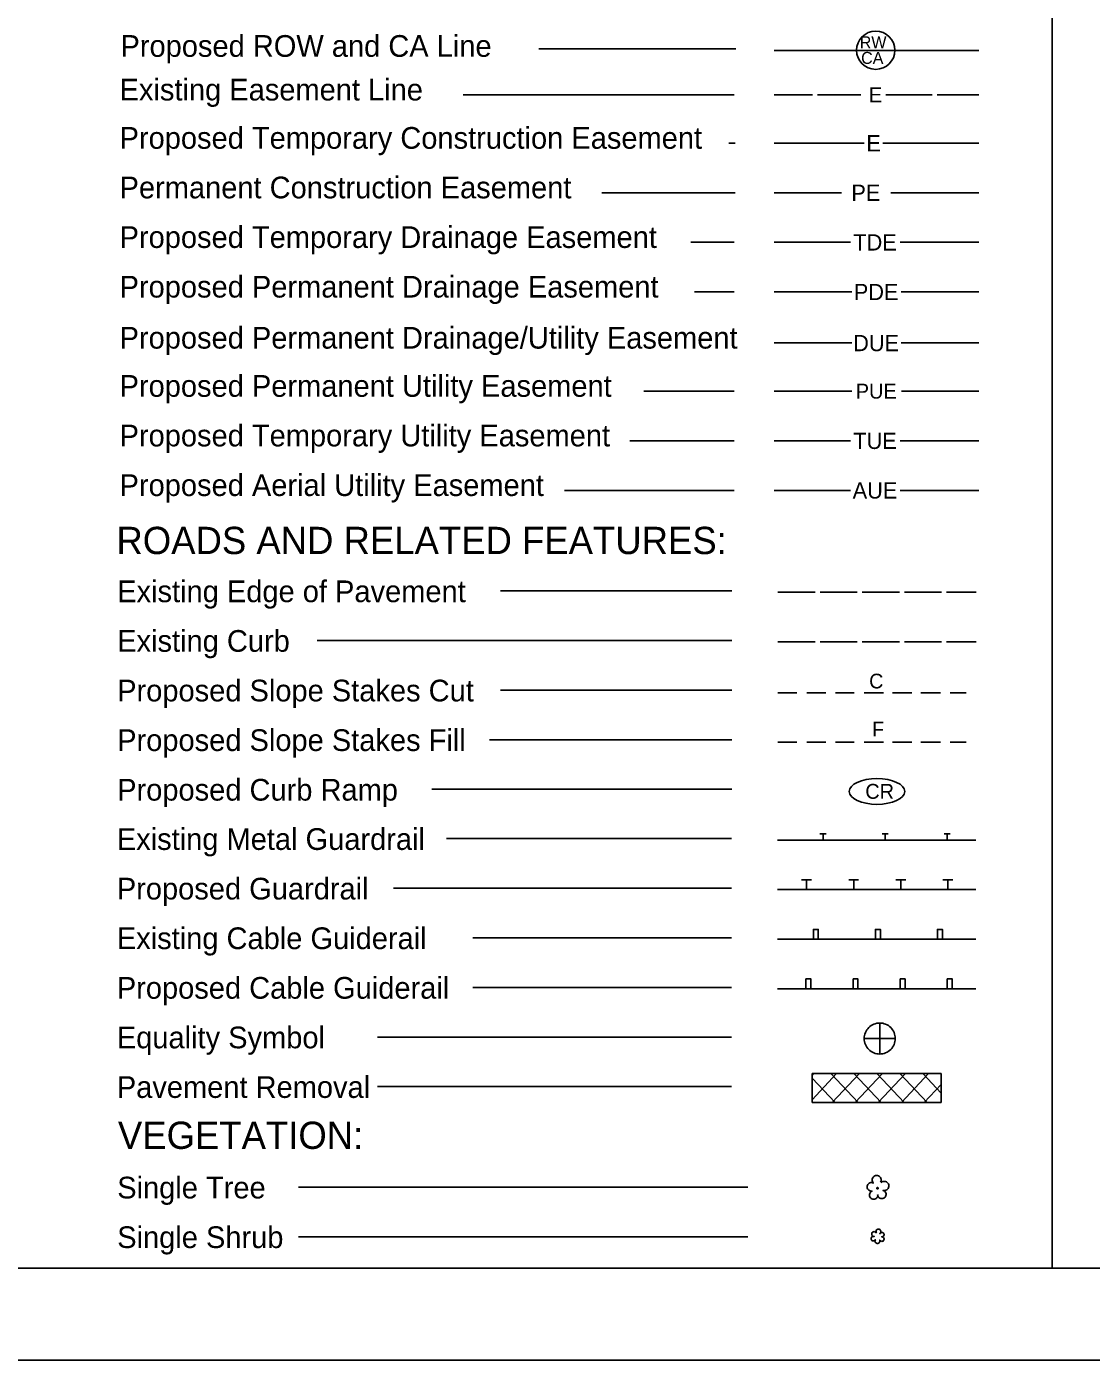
# Model space of a CAD drawing. Extents: x 0 to 3, y 0 to 1.83.
# Drawn here: x 0.722 to 1.443, y 0 to 0.904 of the extents above; entities that cross this region are included whole.
import ezdxf

# ---------------------------------------------------------------- set-up
doc = ezdxf.new("R2010")
doc.units = 0
for name, color, linetype in [('P_RDY_Easement_Permanent', 7, 'Continuous'), ('P_RDY_Easement_Permanent_Drainage_Utility', 7, 'Continuous'), ('Sheet PE Seal Cell', 7, 'Continuous'), ('Sheet_Plan', 7, 'Continuous'), ('Sheet_Symbology', 7, 'Continuous'), ('z - Construction', 7, 'Continuous')]:
    doc.layers.add(name, color=color, linetype=linetype)

msp = doc.modelspace()

# ---------------------------------------------------------------- linework, layer by layer
at = {"layer": 'P_RDY_Easement_Permanent'}
for p, q in [((1.22812, 0.7916), (1.27392, 0.7916)), ((1.30722, 0.7916), (1.35302, 0.7916)), ((1.35302, 0.7916), (1.36684, 0.7916))]:
    msp.add_line(p, q, dxfattribs=at)
at = {"layer": 'P_RDY_Easement_Permanent_Drainage_Utility'}
for p, q in [((1.22812, 0.68973), (1.28075, 0.68973)), ((1.31438, 0.68973), (1.36684, 0.68973))]:
    msp.add_line(p, q, dxfattribs=at)
at = {"layer": 'Sheet PE Seal Cell'}
msp.add_ellipse((1.2979, 0.38567), major_axis=(0.01886, 0), ratio=0.462467, dxfattribs=at)
at = {"layer": 'Sheet_Plan'}
msp.add_line((0.0625, 0.0625), (2.77079, 0.0625), dxfattribs=at)
at = {"layer": 'Sheet_Symbology'}
for p, q in [((1.20222, 0.88925), (1.06878, 0.88925)), ((1.22813, 0.88795), (1.36686, 0.88795)), ((1.20116, 0.85794), (1.01745, 0.85794)), ((1.22812, 0.85794), (1.2542, 0.85794)), ((1.25756, 0.85794), (1.28699, 0.85794)), ((1.30381, 0.85794), (1.33534, 0.85794)), ((1.3387, 0.85794), (1.36684, 0.85794)), ((1.20181, 0.82523), (1.19757, 0.82523)), ((1.22812, 0.82523), (1.23251, 0.82523)), ((1.23251, 0.82523), (1.28926, 0.82523)), ((1.30187, 0.82523), (1.35863, 0.82523)), ((1.35863, 0.82523), (1.36684, 0.82523)), ((1.20181, 0.7916), (1.11133, 0.7916)), ((1.20116, 0.75797), (1.17174, 0.75797)), ((1.22812, 0.75797), (1.23375, 0.75797)), ((1.23375, 0.75797), (1.27999, 0.75797)), ((1.31362, 0.75797), (1.35987, 0.75797)), ((1.35987, 0.75797), (1.36684, 0.75797)), ((1.20116, 0.72434), (1.17424, 0.72434)), ((1.22812, 0.72434), (1.2345, 0.72434)), ((1.2345, 0.72434), (1.28075, 0.72434)), ((1.31438, 0.72434), (1.36062, 0.72434)), ((1.36062, 0.72434), (1.36684, 0.72434)), ((1.20116, 0.65706), (1.13993, 0.65706)), ((1.22812, 0.65706), (1.23457, 0.65706)), ((1.23457, 0.65706), (1.28081, 0.65706)), ((1.31444, 0.65706), (1.36069, 0.65706)), ((1.36069, 0.65706), (1.36684, 0.65706)), ((1.20116, 0.62343), (1.1303, 0.62343)), ((1.22812, 0.62343), (1.23375, 0.62343)), ((1.23375, 0.62343), (1.27999, 0.62343)), ((1.31362, 0.62343), (1.35987, 0.62343)), ((1.35987, 0.62343), (1.36684, 0.62343)), ((1.20116, 0.5898), (1.08605, 0.5898)), ((1.22812, 0.5898), (1.23375, 0.5898)), ((1.23375, 0.5898), (1.27999, 0.5898)), ((1.31362, 0.5898), (1.35987, 0.5898)), ((1.35987, 0.5898), (1.36684, 0.5898)), ((1.19954, 0.52165), (1.04275, 0.52165)), ((1.2307, 0.52068), (1.25592, 0.52068)), ((1.25929, 0.52068), (1.28451, 0.52068)), ((1.28787, 0.52068), (1.3131, 0.52068)), ((1.31646, 0.52068), (1.34168, 0.52068)), ((1.34505, 0.52068), (1.36523, 0.52068)), ((1.19954, 0.48802), (0.91847, 0.48802)), ((1.2307, 0.48705), (1.25592, 0.48705)), ((1.25929, 0.48705), (1.28451, 0.48705)), ((1.28787, 0.48705), (1.3131, 0.48705)), ((1.31646, 0.48705), (1.34168, 0.48705)), ((1.34505, 0.48705), (1.36523, 0.48705)), ((1.19954, 0.45439), (1.04284, 0.45439)), ((1.2307, 0.45262), (1.24348, 0.45262)), ((1.26316, 0.45262), (1.25046, 0.45262)), ((1.28249, 0.45262), (1.26971, 0.45262)), ((1.30225, 0.45262), (1.28914, 0.45262)), ((1.32151, 0.45262), (1.30847, 0.45262)), ((1.34093, 0.45262), (1.32773, 0.45262)), ((1.35825, 0.45262), (1.34749, 0.45262)), ((1.19954, 0.42075), (1.03519, 0.42075)), ((1.2307, 0.41899), (1.24348, 0.41899)), ((1.26316, 0.41899), (1.25046, 0.41899)), ((1.28249, 0.41899), (1.26971, 0.41899)), ((1.30225, 0.41899), (1.28914, 0.41899)), ((1.32151, 0.41899), (1.30847, 0.41899)), ((1.34093, 0.41899), (1.32773, 0.41899)), ((1.35825, 0.41899), (1.34749, 0.41899)), ((1.19954, 0.38712), (0.9962, 0.38712)), ((1.19928, 0.35369), (1.00617, 0.35369)), ((1.23044, 0.35273), (1.36496, 0.35273)), ((1.25926, 0.35693), (1.26346, 0.35693)), ((1.26136, 0.35273), (1.26136, 0.35693)), ((1.3013, 0.35693), (1.3055, 0.35693)), ((1.3034, 0.35273), (1.3034, 0.35693)), ((1.34333, 0.35693), (1.34754, 0.35693)), ((1.34544, 0.35273), (1.34544, 0.35693)), ((1.24679, 0.32574), (1.25352, 0.32574)), ((1.25015, 0.3191), (1.25015, 0.32574)), ((1.27874, 0.32574), (1.28547, 0.32574)), ((1.2821, 0.3191), (1.2821, 0.32574)), ((1.31069, 0.32574), (1.31742, 0.32574)), ((1.31405, 0.3191), (1.31405, 0.32574)), ((1.34264, 0.32574), (1.34937, 0.32574)), ((1.346, 0.3191), (1.346, 0.32574)), ((1.19928, 0.32006), (0.97019, 0.32006)), ((1.36496, 0.3191), (1.23044, 0.3191)), ((1.19928, 0.28643), (1.02389, 0.28643)), ((1.23044, 0.28546), (1.36496, 0.28546)), ((1.19928, 0.2528), (1.02389, 0.2528)), ((1.23044, 0.25183), (1.36496, 0.25183)), ((1.29976, 0.22869), (1.29976, 0.21818)), ((1.19928, 0.21917), (0.95945, 0.21917)), ((1.28925, 0.21818), (1.29976, 0.21818)), ((1.29976, 0.21818), (1.29976, 0.20767)), ((1.29976, 0.21818), (1.31027, 0.21818)), ((1.2539, 0.19443), (1.34151, 0.19443)), ((1.2539, 0.17475), (1.2539, 0.19443)), ((1.2539, 0.19342), (1.25482, 0.19443)), ((1.2539, 0.17669), (1.27046, 0.19443)), ((1.26945, 0.17475), (1.2539, 0.1914)), ((1.28509, 0.17475), (1.26659, 0.19443)), ((1.2676, 0.17475), (1.2861, 0.19443)), ((1.30064, 0.17475), (1.28223, 0.19443)), ((1.28316, 0.17475), (1.30174, 0.19443)), ((1.31628, 0.17475), (1.29778, 0.19443)), ((1.29879, 0.17475), (1.31729, 0.19443)), ((1.33192, 0.17475), (1.31334, 0.19443)), ((1.31443, 0.17475), (1.33285, 0.19443)), ((1.34151, 0.18106), (1.32898, 0.19443)), ((1.34151, 0.19443), (1.34151, 0.17475)), ((1.19928, 0.18554), (0.95945, 0.18554)), ((1.32999, 0.17475), (1.34151, 0.18703)), ((1.34151, 0.17475), (1.2539, 0.17475)), ((1.21034, 0.11736), (0.90577, 0.11736)), ((1.21034, 0.08373), (0.90577, 0.08373))]:
    msp.add_line(p, q, dxfattribs=at)
for points in [[(1.25478, 0.28546), (1.25814, 0.28546), (1.25814, 0.29219), (1.25478, 0.29219)], [(1.29682, 0.28546), (1.30018, 0.28546), (1.30018, 0.29219), (1.29682, 0.29219)], [(1.33886, 0.28546), (1.34222, 0.28546), (1.34222, 0.29219), (1.33886, 0.29219)], [(1.24971, 0.25856), (1.25308, 0.25856), (1.25308, 0.25183), (1.24971, 0.25183)], [(1.28166, 0.25856), (1.28503, 0.25856), (1.28503, 0.25183), (1.28166, 0.25183)], [(1.31361, 0.25856), (1.31698, 0.25856), (1.31698, 0.25183), (1.31361, 0.25183)], [(1.34556, 0.25856), (1.34893, 0.25856), (1.34893, 0.25183), (1.34556, 0.25183)]]:
    msp.add_lwpolyline(points, close=True, dxfattribs=at)
for points in [[(1.30037, 0.12087), (1.30063, 0.12147), (1.30076, 0.12206), (1.3007, 0.12272), (1.30056, 0.12332), (1.30023, 0.12391), (1.2999, 0.12438), (1.29937, 0.12484), (1.29884, 0.1251), (1.29818, 0.1253), (1.29759, 0.1253), (1.29692, 0.12524), (1.29633, 0.12504), (1.2958, 0.12471), (1.29533, 0.12424), (1.295, 0.12372), (1.29474, 0.12312), (1.29467, 0.12252), (1.29467, 0.12186), (1.2948, 0.12127), (1.29507, 0.12067), (1.29546, 0.12014), (1.29494, 0.12041), (1.29434, 0.12054), (1.29374, 0.12047), (1.29315, 0.12034), (1.29262, 0.12007), (1.29209, 0.11968), (1.29176, 0.11921), (1.29143, 0.11868), (1.2913, 0.11815), (1.29123, 0.11749), (1.2913, 0.1169), (1.29156, 0.11637), (1.29189, 0.11584), (1.29229, 0.11544), (1.29282, 0.11511), (1.29335, 0.11484), (1.29394, 0.11478), (1.29454, 0.11478), (1.29401, 0.11451), (1.29355, 0.11412), (1.29322, 0.11365), (1.29295, 0.11306), (1.29282, 0.11246), (1.29275, 0.11187), (1.29288, 0.11127), (1.29315, 0.11074), (1.29348, 0.11021), (1.29388, 0.10981), (1.29441, 0.10948), (1.295, 0.10928), (1.2956, 0.10922), (1.29619, 0.10928), (1.29679, 0.10942), (1.29732, 0.10975), (1.29778, 0.11014), (1.29811, 0.11061), (1.29838, 0.11114), (1.29851, 0.11173)], [(1.29831, 0.11246), (1.29838, 0.1118), (1.29858, 0.1112), (1.29891, 0.11067), (1.29937, 0.11021), (1.2999, 0.10988), (1.3005, 0.10968), (1.30116, 0.10962), (1.30176, 0.10968), (1.30235, 0.10988), (1.30288, 0.11021), (1.30334, 0.11061), (1.30374, 0.11114), (1.30394, 0.11173), (1.30407, 0.11233), (1.30401, 0.11299), (1.30387, 0.11359), (1.30354, 0.11418), (1.30315, 0.11465), (1.30262, 0.11498), (1.30202, 0.11524), (1.30268, 0.11518), (1.30334, 0.11518), (1.30394, 0.11538), (1.30454, 0.11564), (1.30507, 0.11604), (1.30546, 0.11657), (1.30579, 0.11716), (1.30593, 0.11776), (1.30599, 0.11842), (1.30586, 0.11908), (1.30566, 0.11968), (1.30526, 0.12021), (1.3048, 0.12067), (1.30427, 0.121), (1.30361, 0.12127), (1.30301, 0.12133), (1.30235, 0.12133), (1.30169, 0.12113), (1.30116, 0.1208), (1.30063, 0.12041)], [(1.29851, 0.11716), (1.29825, 0.11716), (1.29798, 0.1171), (1.29785, 0.1169), (1.29778, 0.11663), (1.29785, 0.11637), (1.29805, 0.11617), (1.29831, 0.11617), (1.29858, 0.11624), (1.29878, 0.11643), (1.29884, 0.1167), (1.29871, 0.11696), (1.29851, 0.11716)], [(1.29752, 0.08618), (1.29732, 0.08658), (1.29692, 0.08691), (1.29652, 0.08717), (1.29606, 0.08724), (1.2956, 0.08717), (1.29513, 0.08704), (1.29474, 0.08671), (1.29447, 0.08631), (1.29434, 0.08585), (1.29434, 0.08538), (1.29447, 0.08492), (1.29474, 0.08452), (1.29513, 0.08419), (1.2956, 0.08399), (1.29606, 0.08399), (1.2956, 0.08406), (1.29513, 0.08406), (1.29474, 0.08393), (1.29434, 0.08366), (1.29408, 0.08333), (1.29394, 0.08293), (1.29388, 0.08247), (1.29394, 0.08201), (1.29414, 0.08161), (1.29447, 0.08128), (1.29487, 0.08108), (1.29527, 0.08095), (1.29573, 0.08102), (1.29613, 0.08115), (1.29652, 0.08141), (1.29679, 0.08174), (1.29659, 0.08128), (1.29652, 0.08082), (1.29666, 0.08035), (1.29686, 0.07996), (1.29719, 0.07956), (1.29759, 0.07936), (1.29805, 0.07923), (1.29851, 0.07929), (1.29897, 0.07943), (1.29937, 0.07969), (1.29964, 0.08009), (1.29984, 0.08055), (1.29984, 0.08102), (1.29977, 0.08148), (1.29997, 0.08115), (1.30037, 0.08082), (1.30076, 0.08068), (1.30123, 0.08062), (1.30169, 0.08068), (1.30209, 0.08088), (1.30242, 0.08121), (1.30262, 0.08161), (1.30268, 0.08207), (1.30268, 0.08254), (1.30249, 0.08293), (1.30222, 0.08326), (1.30189, 0.08353), (1.30143, 0.08373), (1.30096, 0.08373), (1.30143, 0.08373), (1.30189, 0.08386), (1.30222, 0.08412), (1.30255, 0.08452), (1.30268, 0.08492), (1.30268, 0.08538), (1.30262, 0.08585), (1.30235, 0.08625), (1.30202, 0.08651), (1.30156, 0.08671), (1.30109, 0.08677), (1.3007, 0.08664), (1.30023, 0.08644), (1.29997, 0.08611), (1.29977, 0.08571)], [(1.29957, 0.08571), (1.29997, 0.08591), (1.3003, 0.08631), (1.3005, 0.08671), (1.30056, 0.08717), (1.30056, 0.08764), (1.30037, 0.0881), (1.3001, 0.08843), (1.29977, 0.08876), (1.29931, 0.08889), (1.29884, 0.08896), (1.29838, 0.08889), (1.29798, 0.08869), (1.29759, 0.08836), (1.29739, 0.08797), (1.29725, 0.0875), (1.29725, 0.08704), (1.29732, 0.08658), (1.29759, 0.08618)]]:
    msp.add_lwpolyline(points, dxfattribs=at)
msp.add_circle((1.29706, 0.88821), 0.01298, dxfattribs=at)
for start, end in [(89.99439, 179.99893), (359.99439, 89.99893), (179.99439, 269.99892), (269.99439, 359.99893)]:
    msp.add_arc((1.29976, 0.21818), 0.01051, start, end, dxfattribs=at)
at = {"layer": 'z - Construction'}
for p, q in [((1.41666, 1.77083), (1.41662, 0.0625)), ((0, 0), (2.83333, 0))]:
    msp.add_line(p, q, dxfattribs=at)

# ---------------------------------------------------------------- texts
at = {"layer": 'P_RDY_Easement_Permanent_Drainage_Utility'}
msp.add_text('DUE', height=0.011014, dxfattribs=at).set_placement((1.28176, 0.68418))
at = {"layer": 'Sheet PE Seal Cell'}
msp.add_text('CR', height=0.010089, dxfattribs=at).set_placement((1.28998, 0.3807))
at = {"layer": 'Sheet_Symbology'}
for s, height, p in [('Proposed ROW and CA Line', 0.0147137, (0.78516, 0.88374)), ('RW', 0.008136, (1.28621, 0.8895)), ('CA', 0.008136, (1.28715, 0.87892)), ('Existing Easement Line', 0.0147137, (0.78455, 0.85414)), ('E', 0.01009, (1.29237, 0.8529)), ('Proposed Temporary Construction Easement', 0.0147137, (0.78455, 0.82142)), ('E', 0.01101, (1.2907, 0.81968)), ('Permanent Construction Easement', 0.0147137, (0.78455, 0.78779)), ('PE', 0.011014, (1.28054, 0.78605)), ('Proposed Temporary Drainage Easement', 0.0147137, (0.78455, 0.75416)), ('TDE', 0.011014, (1.28186, 0.75242)), ('Proposed Permanent Drainage Easement', 0.0147137, (0.78455, 0.72053)), ('PDE', 0.011014, (1.28218, 0.71879)), ('Proposed Permanent Drainage/Utility Easement', 0.0147137, (0.78455, 0.68592)), ('Proposed Permanent Utility Easement', 0.0147137, (0.78455, 0.65325)), ('PUE', 0.010089, (1.28352, 0.65201)), ('Proposed Temporary Utility Easement', 0.0147137, (0.78455, 0.61962)), ('TUE', 0.011014, (1.28186, 0.61788)), ('Proposed Aerial Utility Easement', 0.0147137, (0.78455, 0.58599)), ('AUE', 0.011014, (1.28142, 0.58425)), ('ROADS AND RELATED FEATURES:', 0.0184972, (0.78243, 0.54661)), ('Existing Edge of Pavement', 0.0147137, (0.78293, 0.514)), ('Existing Curb', 0.0147137, (0.78293, 0.48037)), ('Proposed Slope Stakes Cut', 0.0147137, (0.78293, 0.44673)), ('C', 0.00997, (1.29258, 0.45554)), ('Proposed Slope Stakes Fill', 0.0147137, (0.78293, 0.4131)), ('F', 0.00997, (1.2946, 0.42296)), ('Proposed Curb Ramp', 0.0147137, (0.78293, 0.37947)), ('Existing Metal Guardrail', 0.0147137, (0.78267, 0.34604)), ('Proposed Guardrail', 0.0147137, (0.78269, 0.31243)), ('Existing Cable Guiderail', 0.0147137, (0.78269, 0.2788)), ('Proposed Cable Guiderail', 0.0147137, (0.78269, 0.24517)), ('Equality Symbol', 0.0147137, (0.78269, 0.21154)), ('Pavement Removal', 0.0147137, (0.78269, 0.17791)), ('VEGETATION:', 0.0184972, (0.78342, 0.14334)), ('Single Tree', 0.0147137, (0.78295, 0.10975)), ('Single Shrub', 0.0147137, (0.78295, 0.07612))]:
    msp.add_text(s, height=height, dxfattribs=at).set_placement(p)

doc.saveas('drawing.dxf')
